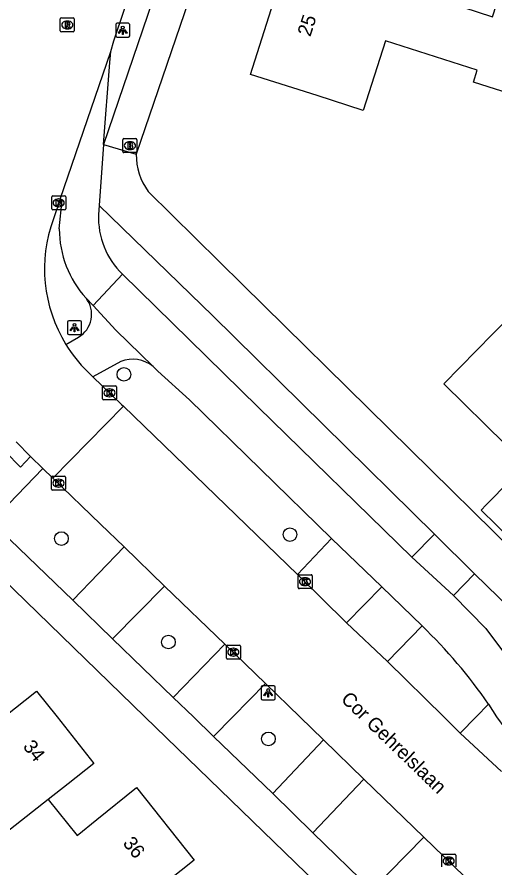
# Model space of a CAD drawing. Extents: x 157321 to 158827, y 386650 to 388532.
# Drawn here: x 157845.6 to 157879.8, y 387489.3 to 387550 of the extents above; entities that cross this region are included whole.
import ezdxf

# ---------------------------------------------------------------- set-up
doc = ezdxf.new("R2010")
doc.units = 0
for name, color, linetype in [('IMGEO_Boom', 7, 'Continuous'), ('IMGEO_Brandkraan', 7, 'Continuous'), ('IMGEO_Fietspad_gesloten', 7, 'Continuous'), ('IMGEO_Fietspad_open', 7, 'Continuous'), ('IMGEO_Kolk', 7, 'Continuous'), ('IMGEO_Lichtpunt', 7, 'Continuous'), ('IMGEO_Openbare_ruimte_label', 7, 'Continuous'), ('IMGEO_Pand', 7, 'Continuous'), ('IMGEO_Pand_nummerreeks', 7, 'Continuous'), ('IMGEO_Parkeervlak_halfverhard', 7, 'Continuous'), ('IMGEO_Rijbaan_lokaal_gesloten', 7, 'Continuous'), ('IMGEO_Rioolput', 7, 'Continuous'), ('IMGEO_Voetpad_open', 7, 'Continuous')]:
    doc.layers.add(name, color=color, linetype=linetype)

msp = doc.modelspace()

# ---------------------------------------------------------------- linework, layer by layer
at = {"layer": 'IMGEO_Boom'}
for centre in [(157853.278, 387524.489), (157865.144, 387513.031), (157848.809, 387512.749), (157856.455, 387505.357), (157863.606, 387498.431)]:
    msp.add_circle(centre, 0.489, dxfattribs=at)
at = {"layer": 'IMGEO_Brandkraan'}
for p, q in [((157853.204, 387540.41), (157853.204, 387541.262)), ((157853.279, 387541.336), (157854.131, 387541.336)), ((157854.205, 387541.262), (157854.205, 387540.41)), ((157853.692, 387541.116), (157853.717, 387541.116)), ((157854.131, 387540.336), (157853.279, 387540.336)), ((157853.715, 387540.556), (157853.69, 387540.556))]:
    msp.add_line(p, q, dxfattribs=at)
for points in [[(157853.204, 387540.41), (157853.204, 387541.262)], [(157853.279, 387541.336), (157854.131, 387541.336)], [(157854.205, 387541.262), (157854.205, 387540.41)], [(157853.552, 387541.036), (157853.552, 387540.636), (157853.765, 387540.636)], [(157853.783, 387541.036), (157853.552, 387541.036)], [(157853.731, 387540.955), (157853.677, 387540.955), (157853.677, 387540.879)], [(157853.677, 387540.879), (157853.73, 387540.879)], [(157853.739, 387540.803), (157853.677, 387540.803), (157853.677, 387540.722)], [(157853.677, 387540.722), (157853.739, 387540.722)], [(157854.131, 387540.336), (157853.279, 387540.336)]]:
    msp.add_lwpolyline(points, dxfattribs=at)
for centre, radius, start, end in [((157853.281, 387541.26), 0.0765, 91.55205, 178.44795), ((157853.281, 387541.26), 0.0765, 91.55205, 178.44795), ((157854.129, 387541.26), 0.0765, 1.55205, 88.44795), ((157854.129, 387541.26), 0.0765, 1.55205, 88.44795), ((157853.732, 387540.917), 0.0379, 267.82845, 90.93552), ((157853.74, 387540.762), 0.0404, 269.87594, 90.50774), ((157853.771, 387540.887), 0.251, 268.66757, 293.53466), ((157853.787, 387540.891), 0.145, 59.4692, 91.53667), ((157853.812, 387540.938), 0.0922, 285.51372, 58.15012), ((157853.817, 387540.746), 0.105, 301.31148, 78.98903), ((157853.281, 387540.412), 0.0765, 181.55205, 268.44795), ((157853.281, 387540.412), 0.0765, 181.55205, 268.44795), ((157854.129, 387540.412), 0.0765, 271.55205, 358.44795), ((157854.129, 387540.412), 0.0765, 271.55205, 358.44795)]:
    msp.add_arc(centre, radius, start, end, dxfattribs=at)
for centre, major_axis, ratio, start_param, end_param in [((157853.691, 387540.836), (-0.387, 0.002), 0.722429, 4.712389, 7.853982), ((157853.716, 387540.836), (-0.39, 0.002), 0.717154, 1.570796, 4.712389)]:
    msp.add_ellipse(centre, major_axis=major_axis, ratio=ratio, start_param=start_param, end_param=end_param, dxfattribs=at)
at = {"layer": 'IMGEO_Fietspad_gesloten'}
for points in [[(157853.173, 387531.642), (157851.074, 387529.416)], [(157853.173, 387531.642), (157857.936, 387526.985), (157862.876, 387522.154), (157873.857, 387511.432)], [(157851.074, 387529.416), (157852.706, 387527.659), (157855.361, 387525.053)], [(157868.118, 387512.747), (157857.97, 387522.673), (157855.706, 387524.713), (157855.361, 387525.053)], [(157868.118, 387512.747), (157871.703, 387509.313)], [(157876.822, 387508.674), (157873.857, 387511.432)], [(157871.703, 387509.313), (157874.591, 387506.503)], [(157876.822, 387508.674), (157879.15, 387506.326), (157881.471, 387503.202)], [(157879.334, 387500.918), (157879.904, 387500), (157881.68, 387497.577)]]:
    msp.add_lwpolyline(points, dxfattribs=at)
msp.add_arc((157849.299, 387480.218), 36.477, 34.57491, 46.10352, dxfattribs=at)
at = {"layer": 'IMGEO_Fietspad_open'}
for points in [[(157851.824, 387540.906), (157852.277, 387546.788), (157852.339, 387547.565)], [(157851.824, 387540.906), (157851.503, 387536.552)], [(157848.658, 387534.883), (157848.858, 387536.937), (157848.709, 387537.001)], [(157851.503, 387536.552), (157851.461, 387535.923)], [(157851.074, 387529.416), (157850.567, 387529.934)], [(157849.127, 387526.63), (157850.026, 387527.146)], [(157853.048, 387525.409), (157851.061, 387524.308)]]:
    msp.add_lwpolyline(points, dxfattribs=at)
for centre, radius, start, end in [((157857.112, 387535.7), 5.656, 177.7419, 225.85169), ((157856.031, 387534.884), 7.373, 180.01122, 222.17548), ((157849.094, 387528.773), 1.875, 299.79835, 38.23858), ((157853.894, 387523.214), 2.353, 51.42297, 111.07726)]:
    msp.add_arc(centre, radius, start, end, dxfattribs=at)
at = {"layer": 'IMGEO_Kolk'}
for p, q in [((157848.114, 387536.321), (157848.114, 387537.173)), ((157848.189, 387537.247), (157849.041, 387537.247)), ((157848.602, 387537.027), (157848.627, 387537.027)), ((157849.115, 387537.173), (157849.115, 387536.321)), ((157848.625, 387536.467), (157848.6, 387536.467)), ((157849.041, 387536.247), (157848.189, 387536.247)), ((157851.823, 387523.668), (157852.675, 387523.668)), ((157851.748, 387522.742), (157851.748, 387523.594)), ((157852.236, 387523.448), (157852.261, 387523.448)), ((157852.749, 387523.594), (157852.749, 387522.742)), ((157852.675, 387522.668), (157851.823, 387522.668)), ((157852.259, 387522.888), (157852.234, 387522.888)), ((157848.097, 387516.286), (157848.097, 387517.138)), ((157848.172, 387517.212), (157849.024, 387517.212)), ((157848.585, 387516.992), (157848.61, 387516.992)), ((157849.098, 387517.138), (157849.098, 387516.286)), ((157848.608, 387516.432), (157848.583, 387516.432)), ((157849.024, 387516.212), (157848.172, 387516.212)), ((157865.72, 387509.245), (157865.72, 387510.097)), ((157865.795, 387510.171), (157866.647, 387510.171)), ((157866.208, 387509.951), (157866.233, 387509.951)), ((157866.721, 387510.097), (157866.721, 387509.245)), ((157866.647, 387509.171), (157865.795, 387509.171)), ((157866.231, 387509.391), (157866.206, 387509.391)), ((157860.598, 387504.204), (157860.598, 387505.056)), ((157860.673, 387505.13), (157861.525, 387505.13)), ((157861.086, 387504.91), (157861.111, 387504.91)), ((157861.599, 387505.056), (157861.599, 387504.204)), ((157861.109, 387504.35), (157861.084, 387504.35)), ((157861.525, 387504.13), (157860.673, 387504.13)), ((157876.063, 387490.203), (157876.915, 387490.203)), ((157875.988, 387489.277), (157875.988, 387490.129)), ((157876.476, 387489.983), (157876.501, 387489.983)), ((157876.989, 387490.129), (157876.989, 387489.277)), ((157876.499, 387489.423), (157876.474, 387489.423))]:
    msp.add_line(p, q, dxfattribs=at)
for points in [[(157848.114, 387536.321), (157848.114, 387537.173)], [(157848.189, 387537.247), (157849.041, 387537.247)], [(157849.115, 387537.173), (157849.115, 387536.321)], [(157848.435, 387536.947), (157848.558, 387536.947), (157848.558, 387536.796), (157848.688, 387536.947), (157848.852, 387536.947), (157848.706, 387536.796), (157848.859, 387536.547), (157848.707, 387536.547), (157848.622, 387536.711), (157848.558, 387536.644), (157848.558, 387536.547), (157848.435, 387536.547), (157848.435, 387536.947)], [(157849.041, 387536.247), (157848.189, 387536.247)], [(157851.823, 387523.668), (157852.675, 387523.668)], [(157851.748, 387522.742), (157851.748, 387523.594)], [(157852.069, 387523.368), (157852.192, 387523.368), (157852.192, 387523.217), (157852.322, 387523.368), (157852.486, 387523.368), (157852.34, 387523.217), (157852.493, 387522.968), (157852.341, 387522.968), (157852.256, 387523.132), (157852.192, 387523.065), (157852.192, 387522.968), (157852.069, 387522.968), (157852.069, 387523.368)], [(157852.749, 387523.594), (157852.749, 387522.742)], [(157852.675, 387522.668), (157851.823, 387522.668)], [(157848.097, 387516.286), (157848.097, 387517.138)], [(157848.172, 387517.212), (157849.024, 387517.212)], [(157849.098, 387517.138), (157849.098, 387516.286)], [(157848.418, 387516.912), (157848.541, 387516.912), (157848.541, 387516.761), (157848.671, 387516.912), (157848.835, 387516.912), (157848.689, 387516.761), (157848.842, 387516.512), (157848.69, 387516.512), (157848.605, 387516.676), (157848.541, 387516.609), (157848.541, 387516.512), (157848.418, 387516.512), (157848.418, 387516.912)], [(157849.024, 387516.212), (157848.172, 387516.212)], [(157865.72, 387509.245), (157865.72, 387510.097)], [(157865.795, 387510.171), (157866.647, 387510.171)], [(157866.041, 387509.871), (157866.164, 387509.871), (157866.164, 387509.72), (157866.294, 387509.871), (157866.458, 387509.871), (157866.312, 387509.72), (157866.465, 387509.471), (157866.313, 387509.471), (157866.228, 387509.635), (157866.164, 387509.568), (157866.164, 387509.471), (157866.041, 387509.471), (157866.041, 387509.871)], [(157866.721, 387510.097), (157866.721, 387509.245)], [(157866.647, 387509.171), (157865.795, 387509.171)], [(157860.598, 387504.204), (157860.598, 387505.056)], [(157860.673, 387505.13), (157861.525, 387505.13)], [(157860.919, 387504.83), (157861.042, 387504.83), (157861.042, 387504.679), (157861.172, 387504.83), (157861.336, 387504.83), (157861.19, 387504.679), (157861.343, 387504.43), (157861.191, 387504.43), (157861.106, 387504.594), (157861.042, 387504.527), (157861.042, 387504.43), (157860.919, 387504.43), (157860.919, 387504.83)], [(157861.599, 387505.056), (157861.599, 387504.204)], [(157861.525, 387504.13), (157860.673, 387504.13)], [(157876.063, 387490.203), (157876.915, 387490.203)], [(157875.988, 387489.277), (157875.988, 387490.129)], [(157876.309, 387489.903), (157876.432, 387489.903), (157876.432, 387489.752), (157876.562, 387489.903), (157876.726, 387489.903), (157876.58, 387489.752), (157876.733, 387489.503), (157876.581, 387489.503), (157876.496, 387489.667), (157876.432, 387489.6), (157876.432, 387489.503), (157876.309, 387489.503), (157876.309, 387489.903)], [(157876.989, 387490.129), (157876.989, 387489.277)]]:
    msp.add_lwpolyline(points, dxfattribs=at)
for centre, start, end in [((157848.191, 387537.171), 91.55205, 178.44795), ((157848.191, 387537.171), 91.55205, 178.44795), ((157849.039, 387537.171), 1.55205, 88.44795), ((157849.039, 387537.171), 1.55205, 88.44795), ((157848.191, 387536.323), 181.55205, 268.44795), ((157848.191, 387536.323), 181.55205, 268.44795), ((157849.039, 387536.323), 271.55205, 358.44795), ((157849.039, 387536.323), 271.55205, 358.44795), ((157851.825, 387523.592), 91.55205, 178.44795), ((157851.825, 387523.592), 91.55205, 178.44795), ((157852.673, 387523.592), 1.55205, 88.44795), ((157852.673, 387523.592), 1.55205, 88.44795), ((157851.825, 387522.744), 181.55205, 268.44795), ((157851.825, 387522.744), 181.55205, 268.44795), ((157852.673, 387522.744), 271.55205, 358.44795), ((157852.673, 387522.744), 271.55205, 358.44795), ((157848.174, 387517.136), 91.55205, 178.44795), ((157848.174, 387517.136), 91.55205, 178.44795), ((157849.022, 387517.136), 1.55205, 88.44795), ((157849.022, 387517.136), 1.55205, 88.44795), ((157848.174, 387516.288), 181.55205, 268.44795), ((157848.174, 387516.288), 181.55205, 268.44795), ((157849.022, 387516.288), 271.55205, 358.44795), ((157849.022, 387516.288), 271.55205, 358.44795), ((157865.797, 387510.095), 91.55205, 178.44795), ((157865.797, 387510.095), 91.55205, 178.44795), ((157866.645, 387510.095), 1.55205, 88.44795), ((157866.645, 387510.095), 1.55205, 88.44795), ((157865.797, 387509.247), 181.55205, 268.44795), ((157865.797, 387509.247), 181.55205, 268.44795), ((157866.645, 387509.247), 271.55205, 358.44795), ((157866.645, 387509.247), 271.55205, 358.44795), ((157860.675, 387505.054), 91.55205, 178.44795), ((157860.675, 387505.054), 91.55205, 178.44795), ((157861.523, 387505.054), 1.55205, 88.44795), ((157861.523, 387505.054), 1.55205, 88.44795), ((157860.675, 387504.206), 181.55205, 268.44795), ((157860.675, 387504.206), 181.55205, 268.44795), ((157861.523, 387504.206), 271.55205, 358.44795), ((157861.523, 387504.206), 271.55205, 358.44795), ((157876.065, 387490.127), 91.55205, 178.44795), ((157876.065, 387490.127), 91.55205, 178.44795), ((157876.913, 387490.127), 1.55205, 88.44795), ((157876.913, 387490.127), 1.55205, 88.44795)]:
    msp.add_arc(centre, 0.0765, start, end, dxfattribs=at)
for centre, major_axis, ratio, start_param, end_param in [((157848.601, 387536.747), (-0.387, 0.002), 0.722429, 4.712389, 7.853982), ((157848.626, 387536.747), (-0.39, 0.002), 0.717154, 1.570796, 4.712389), ((157852.235, 387523.168), (-0.387, 0.002), 0.722429, 4.712389, 7.853982), ((157852.26, 387523.168), (-0.39, 0.002), 0.717154, 1.570796, 4.712389), ((157848.584, 387516.712), (-0.387, 0.002), 0.722429, 4.712389, 7.853982), ((157848.609, 387516.712), (-0.39, 0.002), 0.717154, 1.570796, 4.712389), ((157866.207, 387509.671), (-0.387, 0.002), 0.722429, 4.712389, 7.853982), ((157866.232, 387509.671), (-0.39, 0.002), 0.717154, 1.570796, 4.712389), ((157861.085, 387504.63), (-0.387, 0.002), 0.722429, 4.712389, 7.853982), ((157861.11, 387504.63), (-0.39, 0.002), 0.717154, 1.570796, 4.712389), ((157876.475, 387489.703), (-0.387, 0.002), 0.722429, 4.712389, 7.853982), ((157876.5, 387489.703), (-0.39, 0.002), 0.717154, 1.570796, 4.712389)]:
    msp.add_ellipse(centre, major_axis=major_axis, ratio=ratio, start_param=start_param, end_param=end_param, dxfattribs=at)
at = {"layer": 'IMGEO_Lichtpunt'}
for p, q in [((157852.691, 387549.486), (157852.691, 387548.679)), ((157852.691, 387549.486), (157852.691, 387548.679)), ((157853.593, 387549.581), (157852.785, 387549.581)), ((157853.593, 387549.581), (157852.785, 387549.581)), ((157853.687, 387548.679), (157853.687, 387549.486)), ((157853.687, 387548.679), (157853.687, 387549.486)), ((157852.785, 387548.585), (157853.593, 387548.585)), ((157852.785, 387548.585), (157853.593, 387548.585)), ((157849.243, 387528.231), (157849.243, 387527.424)), ((157849.243, 387528.231), (157849.243, 387527.424)), ((157850.145, 387528.326), (157849.337, 387528.326)), ((157850.145, 387528.326), (157849.337, 387528.326)), ((157850.239, 387527.424), (157850.239, 387528.231)), ((157850.239, 387527.424), (157850.239, 387528.231)), ((157849.337, 387527.33), (157850.145, 387527.33)), ((157849.337, 387527.33), (157850.145, 387527.33)), ((157863.088, 387502.127), (157863.088, 387501.32)), ((157863.088, 387502.127), (157863.088, 387501.32)), ((157863.99, 387502.222), (157863.182, 387502.222)), ((157863.99, 387502.222), (157863.182, 387502.222)), ((157864.084, 387501.32), (157864.084, 387502.127)), ((157864.084, 387501.32), (157864.084, 387502.127)), ((157863.182, 387501.226), (157863.99, 387501.226)), ((157863.182, 387501.226), (157863.99, 387501.226))]:
    msp.add_line(p, q, dxfattribs=at)
for points in [[(157853.065, 387549.15), (157853.104, 387549.122), (157852.916, 387548.86), (157852.878, 387548.887), (157853.065, 387549.15)], [(157853.277, 387549.122), (157853.315, 387549.149), (157853.502, 387548.887), (157853.463, 387548.859), (157853.277, 387549.122)], [(157853.167, 387549.102), (157853.214, 387549.102), (157853.214, 387548.78), (157853.167, 387548.78), (157853.167, 387549.102)], [(157849.617, 387527.895), (157849.656, 387527.867), (157849.468, 387527.605), (157849.43, 387527.632), (157849.617, 387527.895)], [(157849.829, 387527.867), (157849.867, 387527.894), (157850.054, 387527.632), (157850.015, 387527.604), (157849.829, 387527.867)], [(157849.719, 387527.847), (157849.766, 387527.847), (157849.766, 387527.525), (157849.719, 387527.525), (157849.719, 387527.847)], [(157863.462, 387501.791), (157863.501, 387501.763), (157863.313, 387501.501), (157863.275, 387501.528), (157863.462, 387501.791)], [(157863.564, 387501.743), (157863.611, 387501.743), (157863.611, 387501.421), (157863.564, 387501.421), (157863.564, 387501.743)], [(157863.674, 387501.763), (157863.712, 387501.79), (157863.899, 387501.528), (157863.86, 387501.5), (157863.674, 387501.763)]]:
    msp.add_lwpolyline(points, dxfattribs=at)
for centre in [(157853.19, 387549.284), (157849.742, 387528.029), (157863.587, 387501.925)]:
    msp.add_circle(centre, 0.0994, dxfattribs=at)
for centre, start, end in [((157852.785, 387549.486), 90, 180), ((157852.785, 387549.486), 90, 180), ((157853.593, 387549.486), 0, 90), ((157853.593, 387549.486), 0, 90), ((157852.785, 387548.679), 180, 270), ((157852.785, 387548.679), 180, 270), ((157853.593, 387548.679), 270, 0), ((157853.593, 387548.679), 270, 360), ((157849.337, 387528.231), 90, 180), ((157849.337, 387528.231), 90, 180), ((157850.145, 387528.231), 0, 90), ((157850.145, 387528.231), 0, 90), ((157849.337, 387527.424), 180, 270), ((157849.337, 387527.424), 180, 270), ((157850.145, 387527.424), 270, 0), ((157850.145, 387527.424), 270, 360), ((157863.182, 387502.127), 90, 180), ((157863.182, 387502.127), 90, 180), ((157863.99, 387502.127), 0, 90), ((157863.99, 387502.127), 0, 90), ((157863.182, 387501.32), 180, 270), ((157863.182, 387501.32), 180, 270), ((157863.99, 387501.32), 270, 0), ((157863.99, 387501.32), 270, 360)]:
    msp.add_arc(centre, 0.0946, start, end, dxfattribs=at)
at = {"layer": 'IMGEO_Pand'}
for points in [[(157870.381, 387543.356), (157867.077, 387544.41), (157862.313, 387545.929), (157865.138, 387554.79), (157879.615, 387550.034), (157880.776, 387553.674), (157879.585, 387554.054), (157880.651, 387557.4), (157881.842, 387557.021), (157882.043, 387557.65), (157886.807, 387556.131), (157887.78, 387555.821), (157887.656, 387555.433), (157888.926, 387555.028), (157887.758, 387551.365), (157886.488, 387551.769), (157883.88, 387543.59), (157878.259, 387545.383), (157878.532, 387546.239), (157871.967, 387548.332), (157870.381, 387543.356)], [(157884.135, 387515.931), (157880.942, 387512.689), (157878.811, 387514.787), (157879.172, 387515.153), (157882.6, 387518.634), (157881.852, 387519.371), (157881.256, 387518.766), (157880.546, 387519.467), (157876.135, 387523.819), (157879.646, 387527.379), (157883.433, 387531.219), (157888.333, 387526.374), (157889.807, 387527.866), (157891.755, 387525.939)], [(157840.723, 387500.982), (157841.497, 387500), (157842.735, 387498.43), (157844.185, 387499.584), (157844.708, 387500), (157847.039, 387501.855), (157848.502, 387500), (157851.131, 387496.665), (157849.301, 387495.211), (157847.855, 387494.099)], [(157847.855, 387494.099), (157849.927, 387491.519), (157851.35, 387492.67), (157854.168, 387494.95), (157858.299, 387489.761), (157856.427, 387488.291), (157854.983, 387487.157)], [(157847.855, 387494.099), (157842.786, 387490.125)]]:
    msp.add_lwpolyline(points, dxfattribs=at)
at = {"layer": 'IMGEO_Parkeervlak_halfverhard'}
msp.add_lwpolyline([(157865.677, 387510.182), (157868.118, 387512.747)], dxfattribs=at)
at = {"layer": 'IMGEO_Rijbaan_lokaal_gesloten'}
for points in [[(157852.339, 387547.565), (157852.554, 387548.333), (157854.05, 387552.806)], [(157848.709, 387537.001), (157852.339, 387547.565)], [(157848.709, 387537.001), (157848.233, 387535.594)], [(157851.061, 387524.308), (157850.644, 387524.709)], [(157851.061, 387524.308), (157853.111, 387522.339), (157853.248, 387522.206)], [(157848.202, 387517.06), (157853.248, 387522.206)], [(157853.248, 387522.206), (157865.677, 387510.182)], [(157845.579, 387519.655), (157846.603, 387518.614)], [(157846.603, 387518.614), (157847.469, 387517.766)], [(157847.469, 387517.766), (157848.202, 387517.06)], [(157853.293, 387512.15), (157851.607, 387513.781), (157848.202, 387517.06)], [(157853.293, 387512.15), (157856.186, 387509.352)], [(157865.677, 387510.182), (157869.194, 387506.729)], [(157860.479, 387505.201), (157856.186, 387509.352)], [(157869.194, 387506.729), (157872.111, 387503.958)], [(157860.479, 387505.201), (157863.386, 387502.39)], [(157872.111, 387503.958), (157876.145, 387500), (157877.318, 387498.849)], [(157867.545, 387498.364), (157865.855, 387500), (157863.386, 387502.39)], [(157880.26, 387496.098), (157877.318, 387498.849)], [(157867.545, 387498.364), (157870.434, 387495.566)], [(157870.434, 387495.566), (157874.72, 387491.417)], [(157874.72, 387491.417), (157877.604, 387488.619)]]:
    msp.add_lwpolyline(points, dxfattribs=at)
for centre, radius, start, end in [((157857.936, 387532.035), 10.335, 159.85819, 211.53262), ((157857.873, 387531.977), 10.251, 211.44073, 225.15506)]:
    msp.add_arc(centre, radius, start, end, dxfattribs=at)
at = {"layer": 'IMGEO_Rioolput'}
for p, q in [((157848.729, 387549.037), (157848.729, 387549.889)), ((157848.804, 387549.963), (157849.656, 387549.963)), ((157849.217, 387549.743), (157849.242, 387549.743)), ((157849.73, 387549.889), (157849.73, 387549.037)), ((157849.24, 387549.183), (157849.215, 387549.183)), ((157849.656, 387548.963), (157848.804, 387548.963))]:
    msp.add_line(p, q, dxfattribs=at)
for points in [[(157848.729, 387549.037), (157848.729, 387549.889)], [(157848.804, 387549.963), (157849.656, 387549.963)], [(157849.73, 387549.889), (157849.73, 387549.037)], [(157849.318, 387549.661), (157849.066, 387549.663), (157849.066, 387549.263)], [(157849.066, 387549.263), (157849.19, 387549.263), (157849.19, 387549.425), (157849.201, 387549.425)], [(157849.244, 387549.582), (157849.19, 387549.582), (157849.19, 387549.501)], [(157849.19, 387549.501), (157849.242, 387549.501)], [(157849.248, 387549.396), (157849.319, 387549.263), (157849.459, 387549.263), (157849.394, 387549.389)], [(157849.656, 387548.963), (157848.804, 387548.963)]]:
    msp.add_lwpolyline(points, dxfattribs=at)
for centre, radius, start, end in [((157848.806, 387549.887), 0.0765, 91.55205, 178.44795), ((157848.806, 387549.887), 0.0765, 91.55205, 178.44795), ((157849.654, 387549.887), 0.0765, 1.55205, 88.44795), ((157849.654, 387549.887), 0.0765, 1.55205, 88.44795), ((157849.2, 387549.372), 0.0533, 26.02933, 88.69889), ((157849.226, 387549.69), 0.19, 274.7715, 282.96867), ((157849.25, 387549.486), 0.0964, 77.00612, 93.18647), ((157849.264, 387549.543), 0.0378, 276.66336, 79.67722), ((157849.317, 387549.551), 0.109, 350.36119, 89.41601), ((157849.315, 387549.551), 0.112, 277.58423, 350.98172), ((157849.299, 387549.336), 0.108, 29.51342, 73.79051), ((157848.806, 387549.039), 0.0765, 181.55205, 268.44795), ((157848.806, 387549.039), 0.0765, 181.55205, 268.44795), ((157849.654, 387549.039), 0.0765, 271.55205, 358.44795), ((157849.654, 387549.039), 0.0765, 271.55205, 358.44795)]:
    msp.add_arc(centre, radius, start, end, dxfattribs=at)
for centre, major_axis, ratio, start_param, end_param in [((157849.216, 387549.463), (-0.387, 0.002), 0.722429, 4.712389, 7.853982), ((157849.241, 387549.463), (-0.39, 0.002), 0.717154, 1.570796, 4.712389)]:
    msp.add_ellipse(centre, major_axis=major_axis, ratio=ratio, start_param=start_param, end_param=end_param, dxfattribs=at)
at = {"layer": 'IMGEO_Voetpad_open'}
for points in [[(157872.307, 387593.332), (157854.157, 387540.227)], [(157855.672, 387552.253), (157851.824, 387540.906)], [(157851.824, 387540.906), (157854.157, 387540.227)], [(157855.004, 387537.558), (157861.771, 387530.895), (157893.149, 387500), (157909.326, 387484.059)], [(157875.472, 387513.059), (157859.604, 387528.685), (157858.835, 387529.442), (157851.503, 387536.552)], [(157846.603, 387518.614), (157845.895, 387517.85), (157844.802, 387518.963)], [(157843.815, 387513.962), (157847.469, 387517.766)], [(157849.615, 387508.342), (157844.506, 387513.292), (157843.815, 387513.962)], [(157873.857, 387511.432), (157875.472, 387513.059)], [(157875.472, 387513.059), (157878.341, 387510.233)], [(157849.615, 387508.342), (157853.293, 387512.15)], [(157842.827, 387511.58), (157854.778, 387500), (157901.636, 387454.595)], [(157878.341, 387510.233), (157876.822, 387508.674)], [(157883.485, 387505.216), (157878.341, 387510.233)], [(157856.186, 387509.352), (157852.464, 387505.585)], [(157869.194, 387506.729), (157871.703, 387509.313)], [(157852.464, 387505.585), (157849.615, 387508.342)], [(157874.591, 387506.503), (157872.111, 387503.958)], [(157852.464, 387505.585), (157856.798, 387501.392)], [(157856.798, 387501.392), (157860.479, 387505.201)], [(157863.386, 387502.39), (157861.053, 387500), (157859.689, 387498.603)], [(157859.689, 387498.603), (157858.237, 387500), (157856.798, 387501.392)], [(157877.318, 387498.849), (157878.44, 387500), (157879.334, 387500.918)], [(157859.689, 387498.603), (157863.91, 387494.524)], [(157863.91, 387494.524), (157867.545, 387498.364)], [(157866.787, 387491.719), (157870.434, 387495.566)], [(157866.787, 387491.719), (157863.91, 387494.524)], [(157870.986, 387487.615), (157866.787, 387491.719)], [(157874.72, 387491.417), (157870.986, 387487.615)]]:
    msp.add_lwpolyline(points, dxfattribs=at)
msp.add_arc((157858.745, 387540.214), 4.588, 179.83864, 215.37476, dxfattribs=at)

# ---------------------------------------------------------------- texts
at = {"layer": 'IMGEO_Openbare_ruimte_label'}
msp.add_text('Cor Gehrelslaan', height=1, rotation=315.9724, dxfattribs=at).set_placement((157868.725, 387501.198))
at = {"layer": 'IMGEO_Pand_nummerreeks'}
for s, rotation, p in [('25', 72.31873, (157866.599, 387548.576)), ('34', 308.41313, (157846.013, 387497.871)), ('36', 308.52355, (157853.153, 387490.959))]:
    msp.add_text(s, height=1, rotation=rotation, dxfattribs=at).set_placement(p)

doc.saveas('drawing.dxf')
